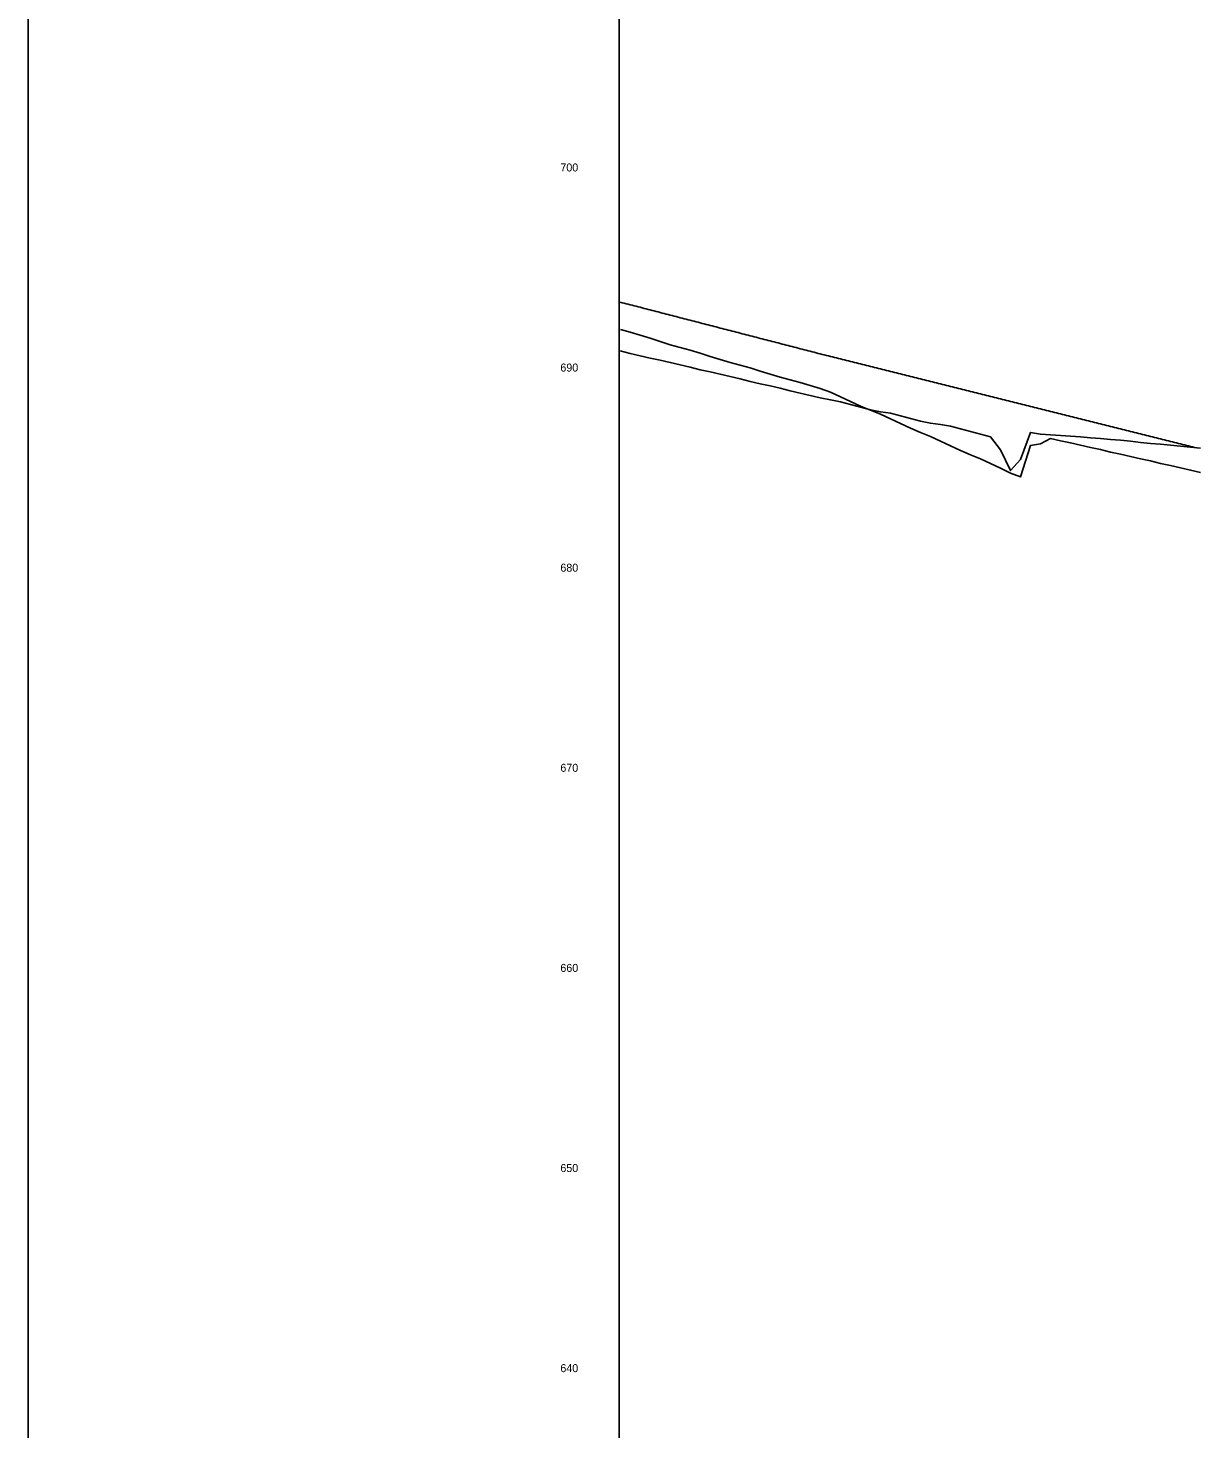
# Model space of a CAD drawing. Extents: x 1733584 to 1737559, y 1214897 to 1219897.
# Drawn here: x 1733584 to 1734168, y 1217770 to 1218470 of the extents above; entities that cross this region are included whole.
import ezdxf

# ---------------------------------------------------------------- set-up
doc = ezdxf.new("R2010")
doc.units = 0
for name, color, linetype in [('Default', 7, 'Continuous'), ('RD_DDB_ElevTX', 7, 'Continuous'), ('RD_DDB_Profile_EX', 7, 'Continuous'), ('RD_Sketch1', 7, 'Continuous'), ('RD_Sketch2', 7, 'Continuous'), ('RD_Sketch8', 7, 'Continuous')]:
    doc.layers.add(name, color=color, linetype=linetype)

msp = doc.modelspace()

# ---------------------------------------------------------------- linework, layer by layer
at = {"layer": 'Default'}
msp.add_line((1733879.77, 1217396.77), (1733879.77, 1219896.77), dxfattribs=at)
at = {"layer": 'RD_DDB_Profile_EX'}
for points in [[(1733880.31, 1218333.46), (1733881.31, 1218333.2), (1733882.31, 1218332.94), (1733883.31, 1218332.68), (1733884.31, 1218332.42), (1733885.31, 1218332.17), (1733886.31, 1218331.91), (1733887.31, 1218331.65), (1733888.31, 1218331.39), (1733889.31, 1218331.13), (1733890.31, 1218330.87), (1733891.31, 1218330.61), (1733892.31, 1218330.36), (1733893.31, 1218330.1), (1733894.31, 1218329.84), (1733895.31, 1218329.58), (1733896.31, 1218329.32), (1733897.31, 1218329.06), (1733898.31, 1218328.8), (1733899.31, 1218328.55), (1733900.31, 1218328.29), (1733901.31, 1218328.03), (1733902.31, 1218327.77), (1733903.31, 1218327.51), (1733904.31, 1218327.25), (1733905.31, 1218326.99), (1733906.31, 1218326.74), (1733907.31, 1218326.48), (1733908.31, 1218326.22), (1733909.31, 1218325.96), (1733910.31, 1218325.7), (1733911.31, 1218325.45), (1733912.31, 1218325.19), (1733913.31, 1218324.93), (1733914.31, 1218324.67), (1733915.31, 1218324.41), (1733916.31, 1218324.15), (1733917.31, 1218323.89), (1733918.31, 1218323.64), (1733919.31, 1218323.38), (1733920.31, 1218323.12), (1733921.31, 1218322.86), (1733922.31, 1218322.6), (1733923.31, 1218322.34), (1733924.31, 1218322.08), (1733925.31, 1218321.83), (1733926.31, 1218321.57), (1733927.31, 1218321.31), (1733928.31, 1218321.05), (1733929.31, 1218320.79), (1733930.31, 1218320.53), (1733931.31, 1218320.28), (1733932.31, 1218320.02), (1733933.31, 1218319.76), (1733934.31, 1218319.5), (1733935.31, 1218319.24), (1733936.31, 1218318.99), (1733937.31, 1218318.73), (1733938.31, 1218318.47), (1733939.31, 1218318.21), (1733940.31, 1218317.95), (1733941.31, 1218317.69), (1733942.31, 1218317.43), (1733943.31, 1218317.18), (1733944.31, 1218316.92), (1733945.31, 1218316.66), (1733946.31, 1218316.4), (1733947.31, 1218316.14), (1733948.31, 1218315.88), (1733949.31, 1218315.63), (1733950.31, 1218315.37), (1733951.31, 1218315.11), (1733952.31, 1218314.85), (1733953.31, 1218314.59), (1733954.31, 1218314.33), (1733955.31, 1218314.08), (1733956.31, 1218313.82), (1733957.31, 1218313.56), (1733958.31, 1218313.3), (1733959.31, 1218313.05), (1733960.31, 1218312.79), (1733961.31, 1218312.53), (1733962.31, 1218312.27), (1733963.31, 1218312.01), (1733964.31, 1218311.75), (1733965.31, 1218311.5), (1733966.31, 1218311.24), (1733967.31, 1218310.98), (1733968.31, 1218310.72), (1733969.31, 1218310.46), (1733970.31, 1218310.2), (1733971.31, 1218309.95), (1733972.31, 1218309.69), (1733973.31, 1218309.43), (1733974.31, 1218309.17), (1733975.31, 1218308.91), (1733976.31, 1218308.65), (1733977.31, 1218308.39), (1733978.31, 1218308.14), (1733979.31, 1218307.88), (1733980.31, 1218307.62)], [(1733980.31, 1218307.62), (1733981.31, 1218307.36), (1733982.31, 1218307.1), (1733983.31, 1218306.85), (1733984.31, 1218306.6), (1733985.31, 1218306.35), (1733986.31, 1218306.1), (1733987.31, 1218305.85), (1733988.31, 1218305.6), (1733989.31, 1218305.35), (1733990.31, 1218305.1), (1733991.31, 1218304.85), (1733992.31, 1218304.6), (1733993.31, 1218304.35), (1733994.31, 1218304.1), (1733995.31, 1218303.85), (1733996.31, 1218303.6), (1733997.31, 1218303.35), (1733998.31, 1218303.1), (1733999.31, 1218302.85), (1734000.31, 1218302.6), (1734001.31, 1218302.35), (1734002.31, 1218302.1), (1734003.31, 1218301.85), (1734004.31, 1218301.6), (1734005.31, 1218301.35), (1734006.31, 1218301.1), (1734007.31, 1218300.85), (1734008.31, 1218300.6), (1734009.31, 1218300.35), (1734010.31, 1218300.1), (1734011.31, 1218299.85), (1734012.31, 1218299.6), (1734013.31, 1218299.35), (1734014.31, 1218299.1), (1734015.31, 1218298.85), (1734016.31, 1218298.6), (1734017.31, 1218298.35), (1734018.31, 1218298.1), (1734019.31, 1218297.85), (1734020.31, 1218297.6), (1734021.31, 1218297.35), (1734022.31, 1218297.1), (1734023.31, 1218296.85), (1734024.31, 1218296.6), (1734025.31, 1218296.35), (1734026.31, 1218296.1), (1734027.31, 1218295.85), (1734028.31, 1218295.6), (1734029.31, 1218295.35), (1734030.31, 1218295.1), (1734031.31, 1218294.85), (1734032.31, 1218294.6), (1734033.31, 1218294.36), (1734034.31, 1218294.11), (1734035.31, 1218293.86), (1734036.31, 1218293.61), (1734037.31, 1218293.36), (1734038.31, 1218293.11), (1734039.31, 1218292.86), (1734040.31, 1218292.61), (1734041.31, 1218292.36), (1734042.31, 1218292.11), (1734043.31, 1218291.86), (1734044.31, 1218291.61), (1734045.31, 1218291.36), (1734046.31, 1218291.11), (1734047.31, 1218290.86), (1734048.31, 1218290.61), (1734049.31, 1218290.36), (1734050.31, 1218290.11), (1734051.31, 1218289.86), (1734052.31, 1218289.61), (1734053.31, 1218289.36), (1734054.31, 1218289.11), (1734055.31, 1218288.86), (1734056.31, 1218288.61), (1734057.31, 1218288.36), (1734058.31, 1218288.11), (1734059.31, 1218287.86), (1734060.31, 1218287.61), (1734061.31, 1218287.36), (1734062.31, 1218287.11), (1734063.31, 1218286.86), (1734064.31, 1218286.61), (1734065.31, 1218286.36), (1734066.31, 1218286.11), (1734067.31, 1218285.86), (1734068.31, 1218285.61), (1734069.31, 1218285.36), (1734070.31, 1218285.11), (1734071.31, 1218284.86), (1734072.31, 1218284.61), (1734073.31, 1218284.36), (1734074.31, 1218284.11), (1734075.31, 1218283.86), (1734076.31, 1218283.61), (1734077.31, 1218283.36), (1734078.31, 1218283.11), (1734079.31, 1218282.87), (1734080.31, 1218282.62)], [(1734080.31, 1218282.62), (1734081.31, 1218282.37), (1734082.31, 1218282.12), (1734083.31, 1218281.87), (1734084.31, 1218281.62), (1734085.31, 1218281.37), (1734086.31, 1218281.12), (1734087.31, 1218280.87), (1734088.31, 1218280.62), (1734089.31, 1218280.37), (1734090.31, 1218280.12), (1734091.31, 1218279.87), (1734092.31, 1218279.62), (1734093.31, 1218279.37), (1734094.31, 1218279.12), (1734095.31, 1218278.87), (1734096.31, 1218278.62), (1734097.31, 1218278.37), (1734098.31, 1218278.12), (1734099.31, 1218277.87), (1734100.31, 1218277.62), (1734101.31, 1218277.37), (1734102.31, 1218277.12), (1734103.31, 1218276.87), (1734104.31, 1218276.62), (1734105.31, 1218276.37), (1734106.31, 1218276.12), (1734107.31, 1218275.87), (1734108.31, 1218275.62), (1734109.31, 1218275.37), (1734110.31, 1218275.12), (1734111.31, 1218274.87), (1734112.31, 1218274.62), (1734113.31, 1218274.37), (1734114.31, 1218274.12), (1734115.31, 1218273.87), (1734116.31, 1218273.62), (1734117.31, 1218273.37), (1734118.31, 1218273.12), (1734119.31, 1218272.87), (1734120.31, 1218272.62), (1734121.31, 1218272.37), (1734122.31, 1218272.12), (1734123.31, 1218271.87), (1734124.31, 1218271.62), (1734125.31, 1218271.37), (1734126.31, 1218271.12), (1734127.31, 1218270.87), (1734128.31, 1218270.62), (1734129.31, 1218270.37), (1734130.31, 1218270.12), (1734131.31, 1218269.87), (1734132.31, 1218269.62), (1734133.31, 1218269.37), (1734134.31, 1218269.12), (1734135.31, 1218268.87), (1734136.31, 1218268.62), (1734137.31, 1218268.37), (1734138.31, 1218268.12), (1734139.31, 1218267.87), (1734140.31, 1218267.62), (1734141.31, 1218267.37), (1734142.31, 1218267.12), (1734143.31, 1218266.87), (1734144.31, 1218266.62), (1734145.31, 1218266.37), (1734146.31, 1218266.12), (1734147.31, 1218265.87), (1734148.31, 1218265.62), (1734149.31, 1218265.37), (1734150.31, 1218265.12), (1734151.31, 1218264.87), (1734152.31, 1218264.62), (1734153.31, 1218264.37), (1734154.31, 1218264.12), (1734155.31, 1218263.87), (1734156.31, 1218263.62), (1734157.31, 1218263.37), (1734158.31, 1218263.12), (1734159.31, 1218262.87), (1734160.31, 1218262.62), (1734161.31, 1218262.37), (1734162.31, 1218262.12), (1734163.31, 1218261.87), (1734164.31, 1218261.62), (1734165.31, 1218261.37), (1734166.31, 1218261.12), (1734167.31, 1218260.87), (1734168.31, 1218260.62)]]:
    msp.add_lwpolyline(points, dxfattribs=at)
at = {"layer": 'RD_Sketch1'}
msp.add_lwpolyline([(1733880.4, 1218319.8), (1733885.31, 1218318.41), (1733890.31, 1218317), (1733895.31, 1218315.49), (1733900.31, 1218313.85), (1733905.31, 1218312.21), (1733910.31, 1218310.81), (1733915.31, 1218309.41), (1733920.31, 1218307.99), (1733925.31, 1218306.37), (1733930.31, 1218304.75), (1733935.31, 1218303.36), (1733940.31, 1218301.97), (1733945.31, 1218300.58), (1733950.31, 1218299.03), (1733955.31, 1218297.43), (1733960.31, 1218296.05), (1733965.31, 1218294.68), (1733970.31, 1218293.3), (1733975.31, 1218291.83), (1733980.31, 1218290.25), (1733985.31, 1218288.49), (1733990.31, 1218286.16), (1733995.31, 1218283.82), (1734000.31, 1218281.49), (1734005.31, 1218279.49), (1734010.31, 1218277.5), (1734015.31, 1218275.15), (1734020.31, 1218272.81), (1734025.31, 1218270.47), (1734030.31, 1218268.39), (1734035.31, 1218266.38), (1734040.31, 1218264.03), (1734045.31, 1218261.68), (1734050.31, 1218259.32), (1734055.31, 1218257.18), (1734060.31, 1218255.14), (1734065.31, 1218252.79), (1734070.31, 1218250.43), (1734075.31, 1218248.07), (1734080.31, 1218246.14), (1734085.31, 1218261.89), (1734090.31, 1218262.62), (1734095.31, 1218265.38), (1734100.31, 1218264.21), (1734105.31, 1218263.1), (1734110.31, 1218262), (1734115.31, 1218260.89), (1734120.31, 1218259.77), (1734125.31, 1218258.57), (1734130.31, 1218257.46), (1734135.31, 1218256.35), (1734140.31, 1218255.24), (1734145.31, 1218254.09), (1734150.31, 1218252.88), (1734155.31, 1218251.76), (1734160.31, 1218250.64), (1734165.31, 1218249.52), (1734170.31, 1218248.36)], dxfattribs=at)
at = {"layer": 'RD_Sketch2'}
msp.add_lwpolyline([(1733880.31, 1218309.08), (1733885.31, 1218307.88), (1733890.31, 1218306.67), (1733895.31, 1218305.47), (1733900.31, 1218304.41), (1733905.31, 1218303.35), (1733910.31, 1218302.14), (1733915.31, 1218300.93), (1733920.31, 1218299.71), (1733925.31, 1218298.6), (1733930.31, 1218297.54), (1733935.31, 1218296.32), (1733940.31, 1218295.1), (1733945.31, 1218293.88), (1733950.31, 1218292.72), (1733955.31, 1218291.64), (1733960.31, 1218290.42), (1733965.31, 1218289.19), (1733970.31, 1218287.96), (1733975.31, 1218286.76), (1733980.31, 1218285.67), (1733985.31, 1218284.64), (1733990.31, 1218283.68), (1733995.31, 1218282.35), (1734000.31, 1218281.02), (1734005.31, 1218279.69), (1734010.31, 1218278.63), (1734015.31, 1218277.91), (1734020.31, 1218276.6), (1734025.31, 1218275.28), (1734030.31, 1218273.96), (1734035.31, 1218272.97), (1734040.31, 1218272.38), (1734045.31, 1218271.43), (1734050.31, 1218270.12), (1734055.31, 1218268.82), (1734060.31, 1218267.51), (1734065.31, 1218266.21), (1734070.31, 1218259.66), (1734075.31, 1218249.27), (1734080.31, 1218254.87), (1734085.31, 1218268.35), (1734090.31, 1218267.45), (1734095.31, 1218267.11), (1734100.31, 1218266.76), (1734105.31, 1218266.42), (1734110.31, 1218266.08), (1734115.31, 1218265.68), (1734120.31, 1218265.37), (1734125.31, 1218264.89), (1734130.31, 1218264.41), (1734135.31, 1218263.93), (1734140.31, 1218263.4), (1734145.31, 1218262.9), (1734150.31, 1218262.41), (1734155.31, 1218261.92), (1734160.31, 1218261.42), (1734165.31, 1218260.93), (1734170.31, 1218260.44)], dxfattribs=at)
at = {"layer": 'RD_Sketch8'}
msp.add_lwpolyline([(1733584.37, 1217120.3), (1737184.37, 1217120.3), (1737184.37, 1219320.3), (1733584.37, 1219320.3)], close=True, dxfattribs=at)

# ---------------------------------------------------------------- texts
at = {"layer": 'RD_DDB_ElevTX'}
for s, p in [('700', (1733850.4, 1218398.77)), ('700', (1733850.4, 1218398.77)), ('700', (1733850.4, 1218398.77)), ('700', (1733850.4, 1218398.77)), ('700', (1733850.4, 1218398.77)), ('690', (1733850.4, 1218298.77)), ('690', (1733850.4, 1218298.77)), ('690', (1733850.4, 1218298.77)), ('690', (1733850.4, 1218298.77)), ('690', (1733850.4, 1218298.77)), ('680', (1733850.4, 1218198.77)), ('680', (1733850.4, 1218198.77)), ('680', (1733850.4, 1218198.77)), ('680', (1733850.4, 1218198.77)), ('680', (1733850.4, 1218198.77)), ('670', (1733850.4, 1218098.77)), ('670', (1733850.4, 1218098.77)), ('670', (1733850.4, 1218098.77)), ('670', (1733850.4, 1218098.77)), ('670', (1733850.4, 1218098.77)), ('660', (1733850.4, 1217998.77)), ('660', (1733850.4, 1217998.77)), ('660', (1733850.4, 1217998.77)), ('660', (1733850.4, 1217998.77)), ('660', (1733850.4, 1217998.77)), ('650', (1733850.4, 1217898.77)), ('650', (1733850.4, 1217898.77)), ('650', (1733850.4, 1217898.77)), ('650', (1733850.4, 1217898.77)), ('650', (1733850.4, 1217898.77)), ('640', (1733850.4, 1217798.77)), ('640', (1733850.4, 1217798.77)), ('640', (1733850.4, 1217798.77)), ('640', (1733850.4, 1217798.77)), ('640', (1733850.4, 1217798.77))]:
    msp.add_text(s, height=4, dxfattribs=at).set_placement(p)

doc.saveas('drawing.dxf')
